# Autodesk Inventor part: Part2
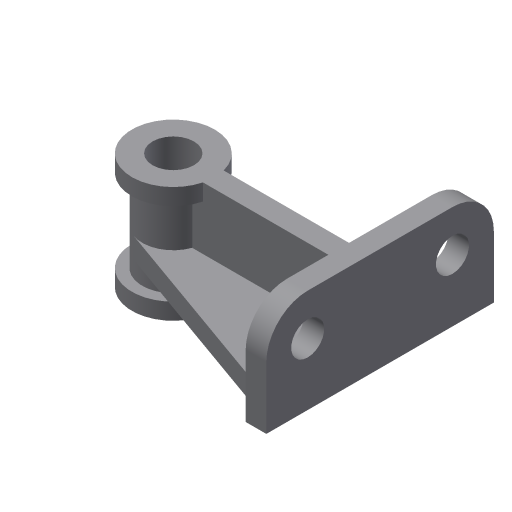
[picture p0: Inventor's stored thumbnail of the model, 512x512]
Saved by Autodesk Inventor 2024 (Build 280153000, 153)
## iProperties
Shininess: 77.0
Length Units: 11269
Angle Units: 11279
Time Units: 11290
Mass Units: 11283
Length Display Precision: 3
Angle Display Precision: 2
Created: 2001-12
Part Number: Part2
Document SubType Name: Modeling
Density: 1 g/cm^3
Material: Generic
Appearance: Default
Density: 0.0
Volumn: 0.0
Area: 0.0
PropertySet Name: Model Information
Control State: 0
Master: False
Checked Out: False
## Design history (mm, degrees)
sketch "Sketch1"
  geometry: L1 (67.049, 55)-(67.049, -55); L2 (60.402, -45.579)-(-27.979, -14.132); L3 (-27.979, 14.132)-(60.402, 45.579); A1 r 10 centre (57.049, -55) between (67.049, -55) and (60.402, -45.579); A2 r 15 centre (-22.951, 0) between (-27.979, 14.132) and (-27.979, -14.132); A3 r 10 centre (57.049, 55) between (60.402, 45.579) and (67.049, 55)
  constraints: 6 end point, 6 point on circle, 6 tangent, 3 centre point, 1 equal length, 1 equal radius, 1 vertical
  dimensions: "d0" = 15 radius of A2; "d1" = 10 radius of A1; "d2" = 90 distance from line of L1 A2.centre; "d3" = 110 distance of L1.start L1.end
extrude "Extrusion1" new body sketch "Sketch1" distance "d4" = 10; taper "d5" = 0 deg
sketch "Sketch2"
  geometry: L1 (0, 110)-(0, 0) reference; L2 (0, 0)-(-30, 0); L3 (-50, 20)-(-50, 90); L4 (-30, 110)-(0, 110); C1 r 8 at (-30, 90); C2 r 8 at (-30, 20); A1 r 20 centre (-30, 20) between (-50, 20) and (-30, 0); A2 r 20 centre (-30, 90) between (-30, 110) and (-50, 90)
  constraints: 6 end point, 4 centre point, 4 point on circle, 4 tangent, 3 perpendicular, 2 coincident, 1 equal radius, 1 parallel
  dimensions: "d6" = 20 radius of A2; "d7" = 50 distance between parallel lines of L1 L3; "d10" = 16 diameter of C1
extrude "Extrusion2" join sketch "Sketch2" distance "d8" = 10; taper "d9" = 0 deg
workplane "Work Plane1"
sketch "Sketch3"
  geometry: C1 r 15 at (-22.951, 0); A1 r 15 centre (-22.951, 0) between (-27.979, 14.132) and (-27.979, -14.132) reference
  constraints: 2 concentric, 1 centre point
extrude "Extrusion3" join sketch "Sketch3" distance "d12" = 56; taper "d13" = 0 deg
sketch "Sketch4"
  geometry: L1 (7.951, 40)-(-57.058, 40); L2 (7.951, 40)-(37.951, 40) reference; L3 (-67.049, 50)-(-67.049, 30) reference; L4 (-77.049, 0)-(-77.049, 30) reference; L5 (-67.049, 0)-(-77.049, 0) reference; A1 r 10 centre (-57.058, 50) between (-67.049, 49.599) and (-57.058, 40)
  constraints: 2 end point, 2 point on circle, 2 point on line, 1 centre point, 1 horizontal, 1 tangent
  dimensions: "d14" = 85 distance from line of L4 L1.start; "d15" = 50 distance from line of L5 A1.centre
feature "Rib1" sketch "Sketch4" dims "d16" = 1, "d17" = 10
sketch "Sketch5"
  geometry: C1 r 20 at (-22.951, 0); 1 further point
  constraints: 1 centre point, 1 coincident
  dimensions: "d18" = 40 diameter of C1
extrude "Extrusion4" join sketch "Sketch5" distance "d19" = 8; taper "d20" = 0 deg
workplane "Work Plane2"
mirror "Mirror1"
sketch "Sketch6"
  geometry: A1 r 20 centre (-22.951, 0) between (-3.586, 5) and (-3.586, -5) reference
hole "Hole1" sketch "Sketch6" diameter "d22" = 20; stored, may be unused: countersink angle "d26" = 82 deg, drill point angle "d28" = 118 deg; dims "d23" = 6, "d24" = 4, "d25" = 2, "d27" = 8
body "Solid1"
other parameters: "d21" = -28
